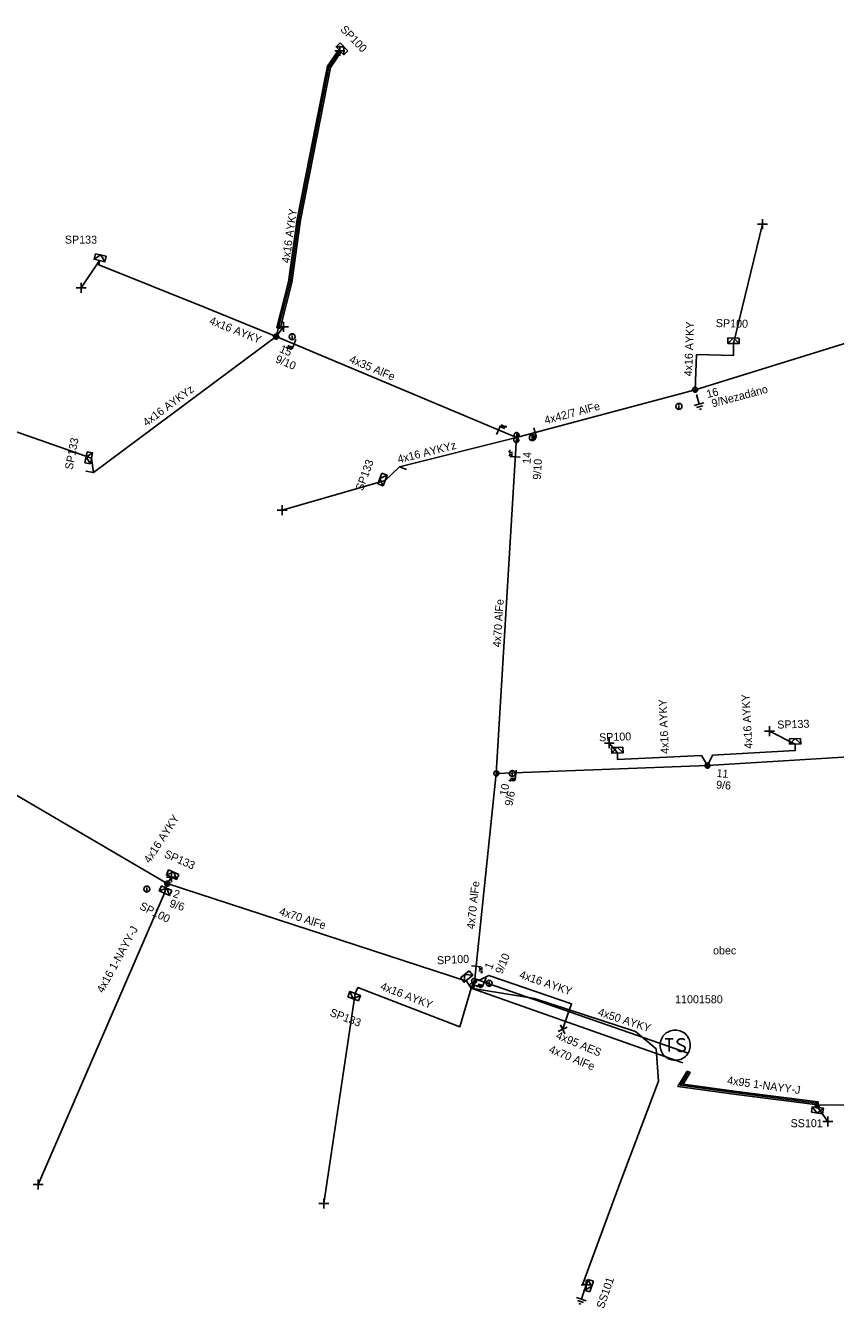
# Model space of a CAD drawing. Extents: x -748492 to -735633, y -1146251 to -1139940.
# Drawn here: x -740507.1 to -740405.9, y -1145496.6 to -1145336.3 of the extents above; entities that cross this region are included whole.
import ezdxf

# ---------------------------------------------------------------- set-up
doc = ezdxf.new("R2010")
doc.units = 0
for name, color, linetype in [('Vrstva 1', 7, 'Continuous'), ('Vrstva 10', 7, 'Continuous'), ('Vrstva 12', 7, 'Continuous'), ('Vrstva 13', 7, 'Continuous'), ('Vrstva 14', 7, 'Continuous'), ('Vrstva 15', 7, 'Continuous'), ('Vrstva 18', 7, 'Continuous'), ('Vrstva 2', 7, 'Continuous'), ('Vrstva 20', 7, 'Continuous'), ('Vrstva 25', 7, 'Continuous'), ('Vrstva 26', 7, 'Continuous'), ('Vrstva 27', 7, 'Continuous'), ('Vrstva 31', 7, 'Continuous'), ('Vrstva 33', 7, 'Continuous'), ('Vrstva 34', 7, 'Continuous'), ('Vrstva 36', 7, 'Continuous'), ('Vrstva 5', 7, 'Continuous'), ('Vrstva 50', 7, 'Continuous'), ('Vrstva 51', 7, 'Continuous'), ('Vrstva 52', 7, 'Continuous'), ('Vrstva 54', 7, 'Continuous'), ('Vrstva 55', 7, 'Continuous'), ('Vrstva 59', 7, 'Continuous'), ('Vrstva 6', 7, 'Continuous'), ('Vrstva 9', 7, 'Continuous')]:
    doc.layers.add(name, color=color, linetype=linetype)

# ---------------------------------------------------------------- blocks, each defined once
blk = doc.blocks.new('NN440')
at = {"layer": 'Vrstva 2'}
for points in [[(0.63, 0), (0.63, 0.06), (0.62, 0.13), (0.6, 0.19), (0.58, 0.25), (0.55, 0.31), (0.51, 0.37), (0.47, 0.42), (0.42, 0.46), (0.37, 0.51), (0.32, 0.54), (0.26, 0.57), (0.2, 0.59), (0.13, 0.61), (0.07, 0.62), (0, 0.63), (-0.06, 0.62), (-0.13, 0.61), (-0.19, 0.59), (-0.26, 0.57), (-0.31, 0.54), (-0.37, 0.51), (-0.42, 0.46), (-0.47, 0.42), (-0.51, 0.37), (-0.54, 0.31), (-0.57, 0.25), (-0.6, 0.19), (-0.62, 0.13), (-0.63, 0.06), (-0.63, 0), (-0.63, -0.07), (-0.62, -0.14), (-0.6, -0.2), (-0.57, -0.26), (-0.54, -0.32), (-0.51, -0.37), (-0.47, -0.43), (-0.42, -0.47), (-0.37, -0.51), (-0.31, -0.55), (-0.26, -0.58), (-0.19, -0.6), (-0.13, -0.62), (-0.06, -0.63), (0, -0.63), (0.07, -0.63), (0.13, -0.62), (0.2, -0.6), (0.26, -0.58), (0.32, -0.55), (0.37, -0.51), (0.42, -0.47), (0.47, -0.43), (0.51, -0.37), (0.55, -0.32), (0.58, -0.26), (0.6, -0.2), (0.62, -0.14), (0.63, -0.07), (0.63, 0)], [(-0.63, 0), (0.63, 0)], [(-0.6, -0.18), (0.57, -0.18)], [(-0.51, -0.32), (0.5, -0.32)], [(-0.37, -0.47), (0.35, -0.47)]]:
    blk.add_lwpolyline(points, dxfattribs=at)
blk = doc.blocks.new('NN450')
at = {"layer": 'Vrstva 2'}
for points in [[(0, 0), (0, 0.07), (-0.01, 0.13), (-0.03, 0.19), (-0.05, 0.25), (-0.08, 0.31), (-0.12, 0.37), (-0.16, 0.42), (-0.21, 0.46), (-0.26, 0.51), (-0.31, 0.54), (-0.37, 0.57), (-0.43, 0.59), (-0.5, 0.61), (-0.56, 0.62), (-0.63, 0.62), (-0.69, 0.62), (-0.75, 0.61), (-0.82, 0.59), (-0.88, 0.57), (-0.94, 0.54), (-0.99, 0.51), (-1.04, 0.46), (-1.09, 0.42), (-1.13, 0.37), (-1.17, 0.31), (-1.2, 0.25), (-1.22, 0.19), (-1.24, 0.13), (-1.25, 0.07), (-1.25, 0), (-1.25, -0.07), (-1.24, -0.13), (-1.22, -0.19), (-1.2, -0.25), (-1.17, -0.31), (-1.13, -0.37), (-1.09, -0.42), (-1.04, -0.46), (-0.99, -0.51), (-0.94, -0.54), (-0.88, -0.57), (-0.82, -0.59), (-0.75, -0.61), (-0.69, -0.62), (-0.62, -0.63), (-0.56, -0.62), (-0.5, -0.61), (-0.43, -0.59), (-0.37, -0.57), (-0.31, -0.54), (-0.26, -0.51), (-0.21, -0.46), (-0.16, -0.42), (-0.12, -0.37), (-0.08, -0.31), (-0.05, -0.25), (-0.03, -0.19), (-0.01, -0.13), (0, -0.07), (0, 0)], [(1.25, 0), (1.25, 0.07), (1.24, 0.13), (1.22, 0.19), (1.2, 0.25), (1.17, 0.31), (1.13, 0.37), (1.09, 0.42), (1.04, 0.46), (0.99, 0.51), (0.94, 0.54), (0.88, 0.57), (0.82, 0.59), (0.75, 0.61), (0.69, 0.62), (0.62, 0.62), (0.56, 0.62), (0.5, 0.61), (0.43, 0.59), (0.37, 0.57), (0.31, 0.54), (0.26, 0.51), (0.21, 0.46), (0.16, 0.42), (0.12, 0.37), (0.08, 0.31), (0.05, 0.25), (0.03, 0.19), (0.01, 0.13), (0, 0.07), (0, 0), (0, -0.07), (0.01, -0.13), (0.03, -0.19), (0.05, -0.25), (0.08, -0.31), (0.12, -0.37), (0.16, -0.42), (0.21, -0.46), (0.26, -0.51), (0.31, -0.54), (0.37, -0.57), (0.43, -0.59), (0.5, -0.61), (0.56, -0.62), (0.63, -0.63), (0.69, -0.62), (0.75, -0.61), (0.82, -0.59), (0.88, -0.57), (0.94, -0.54), (0.99, -0.51), (1.04, -0.46), (1.09, -0.42), (1.13, -0.37), (1.17, -0.31), (1.2, -0.25), (1.22, -0.19), (1.24, -0.13), (1.25, -0.07), (1.25, 0)], [(-1.25, 0), (1.25, 0)], [(-1.23, -0.16), (-0.02, -0.16)], [(-1.16, -0.32), (-0.09, -0.32)], [(-1.03, -0.47), (-0.22, -0.47)], [(0.02, -0.16), (1.23, -0.16)], [(0.09, -0.32), (1.16, -0.32)], [(0.22, -0.47), (1.03, -0.47)]]:
    blk.add_lwpolyline(points, dxfattribs=at)
blk = doc.blocks.new('NN840')
at = {"layer": 'Vrstva 15'}
for points in [[(0, 0.62), (0, -0.63)], [(-0.75, -0.71), (-0.75, -0.66)], [(-0.73, -0.76), (-0.75, -0.71)], [(-0.66, -0.8), (-0.73, -0.76)], [(-0.63, -0.8), (-0.66, -0.8)], [(-0.56, -0.76), (-0.63, -0.8)], [(-0.54, -0.71), (-0.56, -0.76)], [(-0.54, -0.38), (-0.54, -0.71)], [(-0.33, -0.38), (-0.33, -0.8)], [(-0.33, -0.64), (-0.13, -0.38)], [(-0.26, -0.56), (-0.09, -0.8)]]:
    blk.add_lwpolyline(points, dxfattribs=at)
blk = doc.blocks.new('NN770')
at = {"layer": 'Vrstva 10'}
for p, q in [((0, 0.19), (0, 0.26)), ((0, -0.28), (0, 0.11))]:
    blk.add_line(p, q, dxfattribs=at)
blk.add_circle((0, -0.01), 0.375, dxfattribs=at)
blk = doc.blocks.new('NN800')
at = {"layer": 'Vrstva 1'}
for points in [[(-0.44, 0.44), (0.44, -0.44)], [(-0.44, -0.44), (0.44, 0.44)]]:
    blk.add_lwpolyline(points, dxfattribs=at)
blk = doc.blocks.new('NN630')
at = {"layer": 'Vrstva 9'}
for points in [[(0, -0.7), (-0.7, 0)], [(-0.7, -0.7), (-0.7, 0), (0.7, 0), (0.7, -0.7)], [(-0.7, -0.7), (0.7, -0.7)], [(0, -0.7), (0.7, 0)]]:
    blk.add_lwpolyline(points, dxfattribs=at)
blk = doc.blocks.new('NN810')
at = {"layer": 'Vrstva 14'}
for points in [[(0, -0.64), (0, -1.89)], [(0.63, -1.89), (-0.62, -1.89)], [(0.39, -2.2), (-0.4, -2.2)], [(0, -2.52), (-0.12, -2.52)], [(0.14, -2.52), (0, -2.52)]]:
    blk.add_lwpolyline(points, dxfattribs=at)
blk = doc.blocks.new('NN610')
at = {"layer": 'Vrstva 6'}
for points in [[(1.88, 0), (1.87, 0.2), (1.84, 0.39), (1.79, 0.58), (1.72, 0.77), (1.63, 0.94), (1.52, 1.11), (1.4, 1.26), (1.26, 1.4), (1.1, 1.53), (0.94, 1.63), (0.76, 1.72), (0.58, 1.8), (0.19, 1.88), (0.19, 1.88), (-0.01, 1.89), (-0.21, 1.88), (-0.4, 1.85), (-0.59, 1.8), (-0.78, 1.72), (-0.95, 1.63), (-1.12, 1.53), (-1.27, 1.4), (-1.41, 1.26), (-1.54, 1.11), (-1.64, 0.94), (-1.73, 0.77), (-1.8, 0.58), (-1.86, 0.39), (-1.89, 0.2), (-1.9, 0), (-1.89, -0.2), (-1.86, -0.39), (-1.8, -0.58), (-1.73, -0.77), (-1.64, -0.95), (-1.54, -1.11), (-1.41, -1.27), (-1.27, -1.41), (-1.12, -1.53), (-0.95, -1.64), (-0.78, -1.73), (-0.59, -1.8), (-0.4, -1.85), (-0.21, -1.88), (-0.01, -1.89), (0.19, -1.88), (0.39, -1.85), (0.58, -1.8), (0.76, -1.73), (0.94, -1.64), (1.1, -1.53), (1.26, -1.41), (1.4, -1.27), (1.52, -1.11), (1.63, -0.95), (1.72, -0.77), (1.79, -0.58), (1.84, -0.39), (1.87, -0.2), (1.88, 0)], [(-1.27, 0.78), (-0.26, 0.78)], [(-0.76, 0.78), (-0.76, -0.79)], [(1.19, 0.66), (0.94, 0.78), (0.62, 0.78), (0.37, 0.66), (0.24, 0.47), (0.24, 0.4), (0.37, 0.22), (1.12, -0.16), (1.25, -0.32), (1.25, -0.48), (1.12, -0.67), (0.87, -0.79), (0.62, -0.79), (0.49, -0.73), (0.24, -0.6)]]:
    blk.add_lwpolyline(points, dxfattribs=at)
blk = doc.blocks.new('NN510')
at = {"layer": 'Vrstva 2'}
blk.add_lwpolyline([(0, 0), (0, 0.94)], dxfattribs=at)

msp = doc.modelspace()

# ---------------------------------------------------------------- linework, layer by layer
at = {"layer": 'Vrstva 1'}
for points in [[(-740445.8, -1145387.8), (-740423.47, -1145381.82), (-740402.63, -1145375.39), (-740377.18, -1145370.91), (-740356.58, -1145370.31)], [(-740445.8, -1145387.8), (-740475.82, -1145375.19)], [(-740448.31, -1145429.77), (-740445.8, -1145387.8)], [(-740448.31, -1145429.77), (-740421.93, -1145428.79), (-740381.18, -1145426.28), (-740359.35, -1145424.23)], [(-740450.98, -1145455.43), (-740448.31, -1145429.77)], [(-740451.45, -1145456.6), (-740452.05, -1145455.71), (-740489.42, -1145443.54), (-740511.82, -1145430.46)], [(-740424.99, -1145465.94), (-740451.45, -1145456.6)]]:
    msp.add_lwpolyline(points, dxfattribs=at)
at = {"layer": 'Vrstva 20'}
for points in [[(-740475.34, -1145374.16), (-740475.74, -1145374.06), (-740474.27, -1145368.33), (-740473.18, -1145360.55), (-740471.62, -1145352.52), (-740469.42, -1145341.41), (-740468.12, -1145339.51), (-740467.78, -1145339.74), (-740469.03, -1145341.57), (-740471.21, -1145352.6), (-740472.77, -1145360.62), (-740473.87, -1145368.42)], [(-740424.48, -1145466.96), (-740424.1, -1145467.14), (-740424.97, -1145468.58), (-740418.57, -1145469.46), (-740408.15, -1145470.79), (-740407.95, -1145471.45), (-740408.33, -1145471.57), (-740408.45, -1145471.15), (-740418.63, -1145469.86), (-740425.61, -1145468.9)]]:
    msp.add_lwpolyline(points, close=True, dxfattribs=at)
at = {"layer": 'Vrstva 5'}
for points in [[(-740424.35, -1145467.11), (-740425.29, -1145468.74), (-740418.6, -1145469.66), (-740408.3, -1145470.97), (-740408.14, -1145471.51)], [(-740408.14, -1145471.51), (-740407.83, -1145471.24), (-740403.19, -1145471.18), (-740398.03, -1145471.25), (-740388.51, -1145471.64), (-740377.83, -1145472.03), (-740371.51, -1145472.13), (-740357.81, -1145472.68), (-740345.43, -1145473.25), (-740345.21, -1145473.64)]]:
    msp.add_lwpolyline(points, dxfattribs=at)
at = {"layer": 'Vrstva 50'}
msp.add_lwpolyline([(-740424.35, -1145464.72), (-740450.98, -1145455.43)], dxfattribs=at)
at = {"layer": 'Vrstva 52'}
for points in [[(-740475.82, -1145375.19), (-740474.08, -1145368.37), (-740472.98, -1145360.58), (-740471.42, -1145352.56), (-740469.23, -1145341.49), (-740467.85, -1145339.47)], [(-740475.82, -1145375.19), (-740484.7, -1145371.54), (-740497.97, -1145366.24), (-740497.89, -1145365.67)], [(-740423.47, -1145381.82), (-740423.3, -1145377.43), (-740418.68, -1145377.55), (-740418.68, -1145376.05)], [(-740421.93, -1145428.79), (-740421.29, -1145427.5), (-740410.96, -1145426.92), (-740410.96, -1145426.11)], [(-740421.93, -1145428.79), (-740422.68, -1145427.55), (-740433.18, -1145428.02), (-740433.18, -1145427.21)], [(-740489.42, -1145443.54), (-740488.9, -1145442.74)], [(-740489.42, -1145443.54), (-740489.79, -1145444.74)], [(-740450.97, -1145455.43), (-740450.41, -1145455.6), (-740449.26, -1145455.02), (-740438.91, -1145458.55), (-740440.03, -1145461.76)], [(-740451.45, -1145456.6), (-740452.87, -1145461.42), (-740465.61, -1145456.52), (-740465.95, -1145457.27)], [(-740451.45, -1145456.6), (-740443.54, -1145457.9), (-740430.92, -1145462), (-740428.33, -1145464.19), (-740428.04, -1145468.22), (-740432.99, -1145481.35), (-740437.51, -1145493.54), (-740437.07, -1145493.67)]]:
    msp.add_lwpolyline(points, dxfattribs=at)
at = {"layer": 'Vrstva 54'}
for points in [[(-740475.82, -1145375.19), (-740498.66, -1145392.18), (-740498.89, -1145390.39)], [(-740445.8, -1145387.8), (-740460.42, -1145391.47), (-740462.21, -1145393.16)]]:
    msp.add_lwpolyline(points, dxfattribs=at)
at = {"layer": 'Vrstva 59'}
for points in [[(-740418.68, -1145376.05), (-740415.06, -1145361.13)], [(-740497.89, -1145365.67), (-740500.17, -1145369.1)], [(-740475.82, -1145375.19), (-740474.89, -1145373.97)], [(-740498.89, -1145390.39), (-740536, -1145377.38)], [(-740462.21, -1145393.16), (-740475.06, -1145396.88)], [(-740410.96, -1145426.11), (-740414.19, -1145424.5)], [(-740433.18, -1145427.21), (-740434.19, -1145426)], [(-740489.79, -1145444.74), (-740505.56, -1145481.13)], [(-740465.95, -1145457.27), (-740469.88, -1145483.5)], [(-740408.14, -1145471.51), (-740406.88, -1145473.27)]]:
    msp.add_lwpolyline(points, dxfattribs=at)

# ---------------------------------------------------------------- block references
at = {"layer": 'Vrstva 13'}
for name, p, xscale, yscale, rotation in [('NN440', (-740475.82, -1145375.19), 0.5, 0.5, -22.90715556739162), ('NN440', (-740423.47, -1145381.82), 0.5, 0.5, 14.997516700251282), ('NN450', (-740445.8, -1145387.8), 0.5, 0.4999999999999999, 86.57847778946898), ('NN440', (-740421.93, -1145428.79), 0.49999999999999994, 0.5000000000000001, -4.850533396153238), ('NN440', (-740448.31, -1145429.77), 0.5, 0.5000000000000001, 78.93954163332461), ('NN440', (-740489.42, -1145443.54), 0.49999999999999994, 0.5000000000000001, -17.976672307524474), ('NN450', (-740451.2, -1145455.98), 0.5000000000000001, 0.5, 67.64688610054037)]:
    msp.add_blockref(name, p, dxfattribs=dict(at, xscale=xscale, yscale=yscale, rotation=rotation))
for p, rotation in [((-740460.42, -1145391.47), -110.16260273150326), ((-740498.66, -1145392.18), 79.10524723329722)]:
    msp.add_blockref('NN510', p, dxfattribs=dict(at, rotation=rotation))
at = {"layer": 'Vrstva 15'}
for p, rotation in [((-740423.47, -1145381.82), 14.997516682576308), ((-740437.07, -1145493.67), -19.063616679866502)]:
    msp.add_blockref('NN810', p, dxfattribs=dict(at, rotation=rotation))
at = {"layer": 'Vrstva 18'}
for p, rotation in [((-740473.59, -1145376.13), -22.90715556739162), ((-740448.03, -1145386.86), 157.09284430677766), ((-740443.46, -1145387.18), 14.997516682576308), ((-740445.94, -1145390.22), -93.42152221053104), ((-740445.89, -1145429.97), -4.850533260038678), ((-740450.81, -1145453.86), 83.89660280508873), ((-740449.83, -1145455.9), -22.667388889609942)]:
    msp.add_blockref('NN840', p, dxfattribs=dict(at, rotation=rotation))
at = {"layer": 'Vrstva 25'}
msp.add_blockref('NN610', (-740425.95, -1145463.73), dxfattribs=at)
at = {"layer": 'Vrstva 31'}
for p, rotation in [((-740467.85, -1145339.47), 133.9145249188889), ((-740497.89, -1145365.67), 166.98119757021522), ((-740418.68, -1145376.05), 178.6212388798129), ((-740498.89, -1145390.39), -100.89475279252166), ((-740462.21, -1145393.16), -110.1626027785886), ((-740433.18, -1145427.21), -177.98373045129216), ((-740410.96, -1145426.11), -178.17971941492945), ((-740488.9, -1145442.74), 156.27099445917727), ((-740489.79, -1145444.74), 155.03011654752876), ((-740451.79, -1145455.42), -140.8678716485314), ((-740465.95, -1145457.27), -20.939183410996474), ((-740408.14, -1145471.51), -7.2482194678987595), ((-740437.07, -1145493.67), 70.9363833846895)]:
    msp.add_blockref('NN630', p, dxfattribs=dict(at, rotation=rotation))
at = {"layer": 'Vrstva 34'}
for p, rotation in [((-740467.85, -1145339.47), 45), ((-740415.06, -1145361.13), 45), ((-740500.17, -1145369.1), 45), ((-740474.89, -1145373.97), 45), ((-740475.06, -1145396.88), 45), ((-740414.19, -1145424.5), 44.99999995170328), ((-740434.19, -1145426), 44.99999995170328), ((-740488.9, -1145442.74), 45.00000009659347), ((-740440.03, -1145461.76), -109.30513212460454), ((-740406.88, -1145473.27), 45), ((-740505.56, -1145481.13), 45), ((-740469.88, -1145483.5), 45), ((-740437.07, -1145493.67), 45)]:
    msp.add_blockref('NN800', p, dxfattribs=dict(at, rotation=rotation))
at = {"layer": 'Vrstva 36'}
for p in [(-740473.82, -1145375.19), (-740425.49, -1145383.9), (-740443.8, -1145387.8), (-740446.31, -1145429.77), (-740491.98, -1145444.21), (-740449.2, -1145455.98)]:
    msp.add_blockref('NN770', p, dxfattribs=at)

# ---------------------------------------------------------------- texts
at = {"layer": 'Vrstva 12'}
for s, rotation, p in [('9/10', 337.093, (-740476.01, -1145378.36)), ('9/Nezadáno', 14.998, (-740421.26, -1145384.04)), ('9/10', 86.578, (-740442.76, -1145393.09)), ('9/6', 355.149, (-740420.88, -1145431.65)), ('9/6', 78.94, (-740446.32, -1145433.9)), ('9/6', 342.023, (-740489.23, -1145446.41)), ('9/10', 67.647, (-740447.58, -1145454.92))]:
    msp.add_text(s, height=1, rotation=rotation, dxfattribs=at).set_placement(p)
at = {"layer": 'Vrstva 14'}
for s, rotation, p in [('15', 337.093, (-740475.49, -1145377.09)), ('16', 14.998, (-740421.9, -1145382.88)), ('14', 86.578, (-740444.03, -1145391.12)), ('11', 355.149, (-740420.82, -1145430.21)), ('10', 78.94, (-740446.95, -1145432.63)), ('2', 342.023, (-740488.77, -1145445.19)), ('1', 67.647, (-740448.9, -1145454.34))]:
    msp.add_text(s, height=1, rotation=rotation, dxfattribs=at).set_placement(p)
at = {"layer": 'Vrstva 2'}
for s, rotation, p in [('4x35 AlFe', 337.093, (-740466.77, -1145378.38)), ('4x42/7 AlFe', 14.998, (-740442.16, -1145386.15)), ('4x70 AlFe', 86.258, (-740447.77, -1145414.03)), ('4x70 AlFe', 83.924, (-740451.04, -1145449.26)), ('4x70 AlFe', 342.023, (-740475.52, -1145447.41)), ('4x70 AlFe', 337.648, (-740441.83, -1145464.61))]:
    msp.add_text(s, height=1, rotation=rotation, dxfattribs=at).set_placement(p)
at = {"layer": 'Vrstva 26'}
msp.add_text('11001580', height=1, dxfattribs=at).set_placement((-740425.97, -1145458.49))
at = {"layer": 'Vrstva 27'}
msp.add_text('obec', height=1, dxfattribs=at).set_placement((-740421.23, -1145452.39))
at = {"layer": 'Vrstva 33'}
for s, rotation, p in [('SP100', 313.915, (-740467.87, -1145336.87)), ('SP133', 359.832, (-740502.22, -1145363.57)), ('SP100', 358.621, (-740420.89, -1145373.99)), ('SP133', 79.105, (-740501.26, -1145391.88)), ('SP133', 69.837, (-740465, -1145394.54)), ('SP133', 1.82, (-740413.19, -1145424.18)), ('SP100', 2.016, (-740435.45, -1145425.77)), ('SP133', 336.271, (-740489.91, -1145440.19)), ('SP100', 333.131, (-740492.98, -1145446.67)), ('SP100', 2.895, (-740455.7, -1145453.63)), ('SP133', 339.061, (-740469.2, -1145460.03)), ('SS101', 70.936, (-740434.89, -1145496.72))]:
    msp.add_text(s, height=1, rotation=rotation, dxfattribs=at).set_placement(p)
msp.add_text('SS101', height=1, dxfattribs=at).set_placement((-740411.54, -1145473.98))
at = {"layer": 'Vrstva 51'}
msp.add_text('4x95 AES', height=1, rotation=337.312, dxfattribs=at).set_placement((-740440.94, -1145462.87))
at = {"layer": 'Vrstva 54'}
for s, rotation, p in [('4x16 AYKY', 81.983, (-740474.17, -1145366.06)), ('4x16 AYKY', 338.347, (-740484.27, -1145373.57)), ('4x16 AYKY', 87.742, (-740423.86, -1145380.17)), ('4x16 AYKY', 93.197, (-740416.3, -1145426.67)), ('4x16 AYKY', 92.518, (-740426.74, -1145427.31)), ('4x16 AYKY', 56.829, (-740491.62, -1145441.08)), ('4x16 1-NAYY-J', 61.35, (-740497.45, -1145457.29)), ('4x16 AYKY', 341.167, (-740445.52, -1145455.31)), ('4x16 AYKY', 338.955, (-740462.89, -1145456.74)), ('4x50 AYKY', 342.029, (-740435.7, -1145460))]:
    msp.add_text(s, height=1, rotation=rotation, dxfattribs=at).set_placement(p)
at = {"layer": 'Vrstva 55'}
for rotation, p in [(36.652, (-740492.02, -1145386.45)), (14.081, (-740460.52, -1145391.02))]:
    msp.add_text('4x16 AYKYz', height=1, rotation=rotation, dxfattribs=at).set_placement(p)
at = {"layer": 'Vrstva 6'}
msp.add_text('4x95 1-NAYY-J', height=1, rotation=352.17, dxfattribs=at).set_placement((-740419.51, -1145468.59))

doc.saveas('drawing.dxf')
